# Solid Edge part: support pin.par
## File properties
Author: Sarvanan
Template: sync ansi part.par
Last saved by: CADCIM
Revision: 19
Application: Solid Edge
Accuracy: 0.990
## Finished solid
Body 1: solid body, 9 faces, 8 edges, 0 vertices.
  Faces by surface: plane 4, cylinder 3, cone 2
  Edges by curve: circle 8
Bounding box of the edges (mm): 6.350 x 6.350 x 66.675, from (12.0753, 27.1097, -66.675) to (18.4253, 33.4597, 0).
Cylindrical faces by radius (mm): R2.413 x2, R3.175 x1
Conical faces (half-angle, radius in mm at the cone's reference point): 44.9733 deg R1.6517 x2
Planar faces by outward normal: +z 2, -z 2
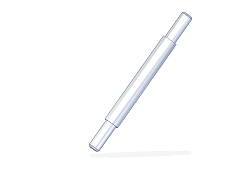
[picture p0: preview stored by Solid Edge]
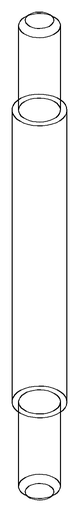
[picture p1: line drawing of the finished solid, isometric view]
